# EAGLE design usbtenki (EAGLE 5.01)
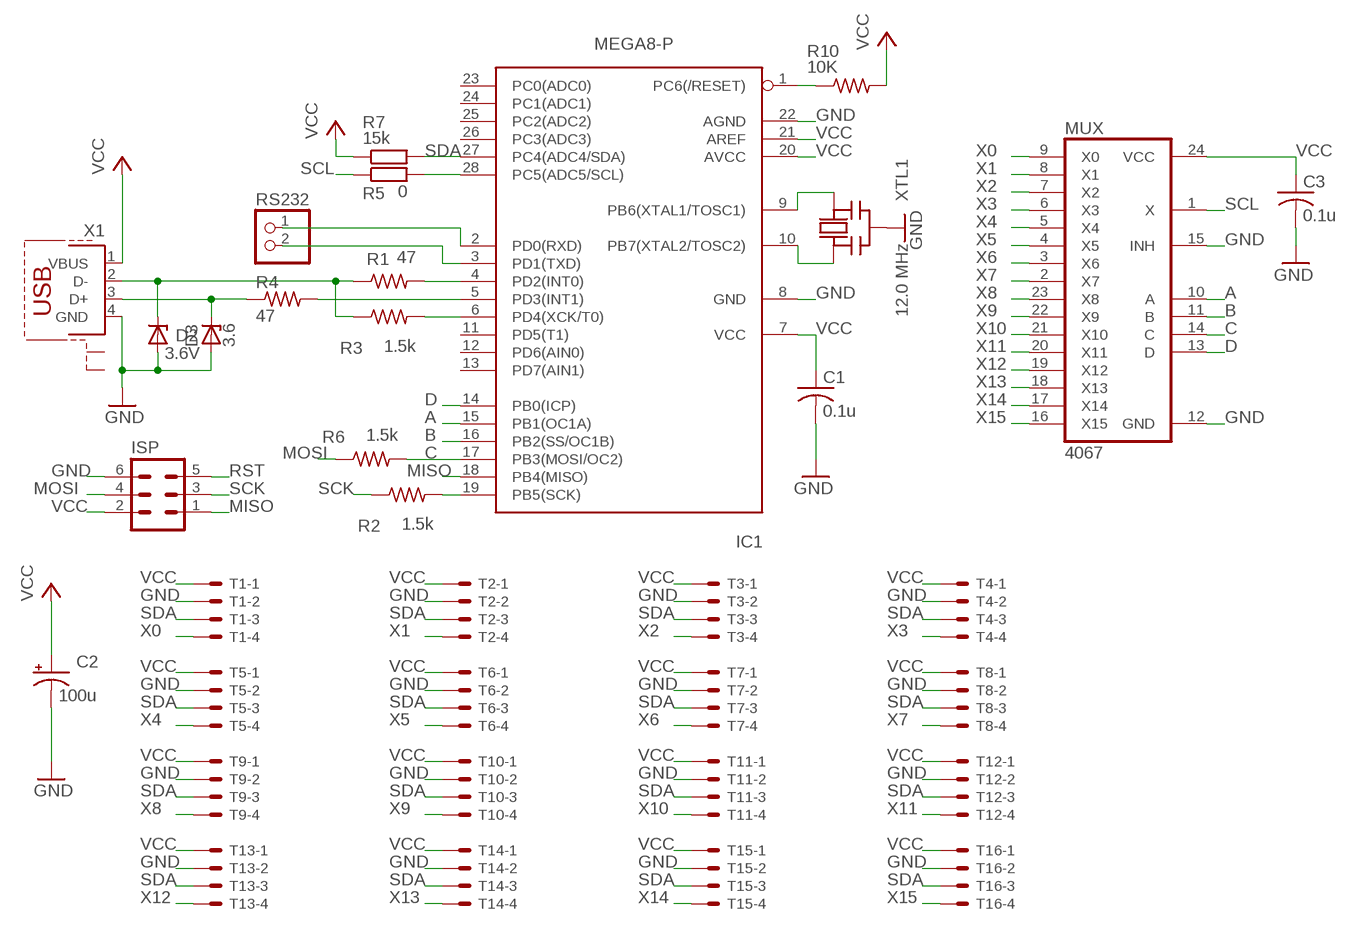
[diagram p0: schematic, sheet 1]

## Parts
C1  0.1u  C-US025-025X050  [C025-025X050]
C2  100u  CPOL-USE2.5-5  [E2,5-5]
C3  0.1u  C-US025-025X050  [C025-025X050]
D2  3.6V  ZENER-DIODEDO35Z10  [DO35Z10]
D3  3.6  ZENER-DIODEDO34-7  [DO34Z7]
IC1  MEGA8-P  [DIL28-3]
ISP  MA03-2  [MA03-2]
MUX  4067  [DIL24-6]
R1  47  R-US_0207/10  [0207/10]
R2  1.5k  R-US_0207/10  [0207/10]
R3  1.5k  R-US_0207/10  [0207/10]
R4  47  R-US_0207/5V  [0207/5V]
R5  0  R-EU_0207/12  [0207/12]
R6  1.5k  R-US_0207/10  [0207/10]
R7  15k  R-EU_0207/12  [0207/12]
R10  10K  R-US_0207/10  [0207/10]
RS232  PINHD-1X2  [1X02]
T1  C-GRID-04-70543  [70543-04]
T2  C-GRID-04-70543  [70543-04]
T3  C-GRID-04-70543  [70543-04]
T4  C-GRID-04-70543  [70543-04]
T5  C-GRID-04-70543  [70543-04]
T6  C-GRID-04-70543  [70543-04]
T7  C-GRID-04-70543  [70543-04]
T8  C-GRID-04-70543  [70543-04]
T9  C-GRID-04-70543  [70543-04]
T10  C-GRID-04-70543  [70543-04]
T11  C-GRID-04-70543  [70543-04]
T12  C-GRID-04-70543  [70543-04]
T13  C-GRID-04-70543  [70543-04]
T14  C-GRID-04-70543  [70543-04]
T15  C-GRID-04-70543  [70543-04]
T16  C-GRID-04-70543  [70543-04]
X1  USB-B_SHIELDED  [PN61729-S]
XTL1  12.0 MHz  CERMOSCILL  [CERM_OSC]

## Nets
A: IC1.15(PB1(OC1A)) MUX.10(A)
B: IC1.16(PB2(SS/OC1B)) MUX.11(B)
C: IC1.17(PB3(MOSI/OC2)) MUX.14(C) R6.2
D: IC1.14(PB0(ICP)) MUX.13(D)
D+: D3.C R4.1 X1.3(D+)
D-: D2.C R1.1 R3.1 X1.2(D-)
GND: C1.2 C2.- C3.2 D2.A D3.A IC1.8(GND) IC1.22(AGND) ISP.6 MUX.12(GND) MUX.15(INH) T1.2 T2.2 T3.2 T4.2 T5.2 T6.2 T7.2 T8.2 T9.2 T10.2 T11.2 T12.2 T13.2 T14.2 T15.2 T16.2 X1.4(GND) XTL1.P$2(GND)
MISO: IC1.18(PB4(MISO)) ISP.1
MOSI: ISP.4 R6.1
N$1: IC1.28(PC5(ADC5/SCL)) R5.2
N$2: IC1.3(PD1(TXD)) RS232.2
N$3: IC1.4(PD2(INT0)) R1.2
N$4: IC1.9(PB6(XTAL1/TOSC1)) XTL1.P$1(IN)
N$5: IC1.10(PB7(XTAL2/TOSC2)) XTL1.P$3(OUT)
N$6: IC1.5(PD3(INT1)) R4.2
N$7: IC1.6(PD4(XCK/T0)) R3.2
N$8: IC1.19(PB5(SCK)) R2.2
N$9: IC1.2(PD0(RXD)) RS232.1
RST: IC1.1(PC6(/RESET)) ISP.5 R10.1
SCK: ISP.3 R2.1
SCL: MUX.1(X) R5.1
SDA: IC1.27(PC4(ADC4/SDA)) T1.3 T2.3 T3.3 T4.3 T5.3 T6.3 T7.3 T8.3 T9.3 T10.3 T11.3 T12.3 T13.3 T14.3 T15.3 T16.3
VCC: C1.1 C2.+ C3.1 IC1.7(VCC) IC1.20(AVCC) IC1.21(AREF) ISP.2 MUX.24(VCC) R7.1 R10.2 T1.1 T2.1 T3.1 T4.1 T5.1 T6.1 T7.1 T8.1 T9.1 T10.1 T11.1 T12.1 T13.1 T14.1 T15.1 T16.1 X1.1(VBUS)
X0: MUX.9(X0) T1.4
X1: MUX.8(X1) T2.4
X2: MUX.7(X2) T3.4
X3: MUX.6(X3) T4.4
X4: MUX.5(X4) T5.4
X5: MUX.4(X5) T6.4
X6: MUX.3(X6) T7.4
X7: MUX.2(X7) T8.4
X8: MUX.23(X8) T9.4
X9: MUX.22(X9) T10.4
X10: MUX.21(X10) T11.4
X11: MUX.20(X11) T12.4
X12: MUX.19(X12) T13.4
X13: MUX.18(X13) T14.4
X14: MUX.17(X14) T15.4
X15: MUX.16(X15) T16.4
Unconnected: IC1.11(PD5(T1)) IC1.12(PD6(AIN0)) IC1.13(PD7(AIN1)) IC1.23(PC0(ADC0)) IC1.24(PC1(ADC1)) IC1.25(PC2(ADC2)) IC1.26(PC3(ADC3)) R7.2 X1.S1 X1.S2

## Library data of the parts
C1 C3 = rcl-ez:C-US: CAPACITOR, American symbol
C2 = rcl-ez:CPOL-US: POLARIZED CAPACITOR, American symbol
D2 D3 = diode:ZENER-DIODE: Z-Diode
IC1 = atmel:MEGA8-P: MICROCONTROLLER 8 Kbytes FLASH, 1 kbytes SRAM, 512 bytes EEPROM, USART, 4-channel 10 bit ADC, 2-channel 8 bit ADC Pin compatible with Atmega48, ATMega88, ATMega168 Source: avr.lbr
ISP = con-lstb:MA03-2: PIN HEADER
MUX = marios:4067: 16-channel ANALOG MULTIPLEXER
R1-R3 R6 R10 = rcl-ez:R-US_: RESISTOR, American symbol
R4 = resistor:R-US_: RESISTOR, American symbol
R5 R7 = resistor:R-EU_: RESISTOR, European symbol
RS232 = pinhead:PINHD-1X2: PIN HEADER
T1-T16 = con-molex:C-GRID-04: CONNECTOR wire to board 2.54 mm (0.100") pitch header
X1 = marios:USB-B_SHIELDED: BERG USB connector
XTL1 = minimidi:CERMOSCILL

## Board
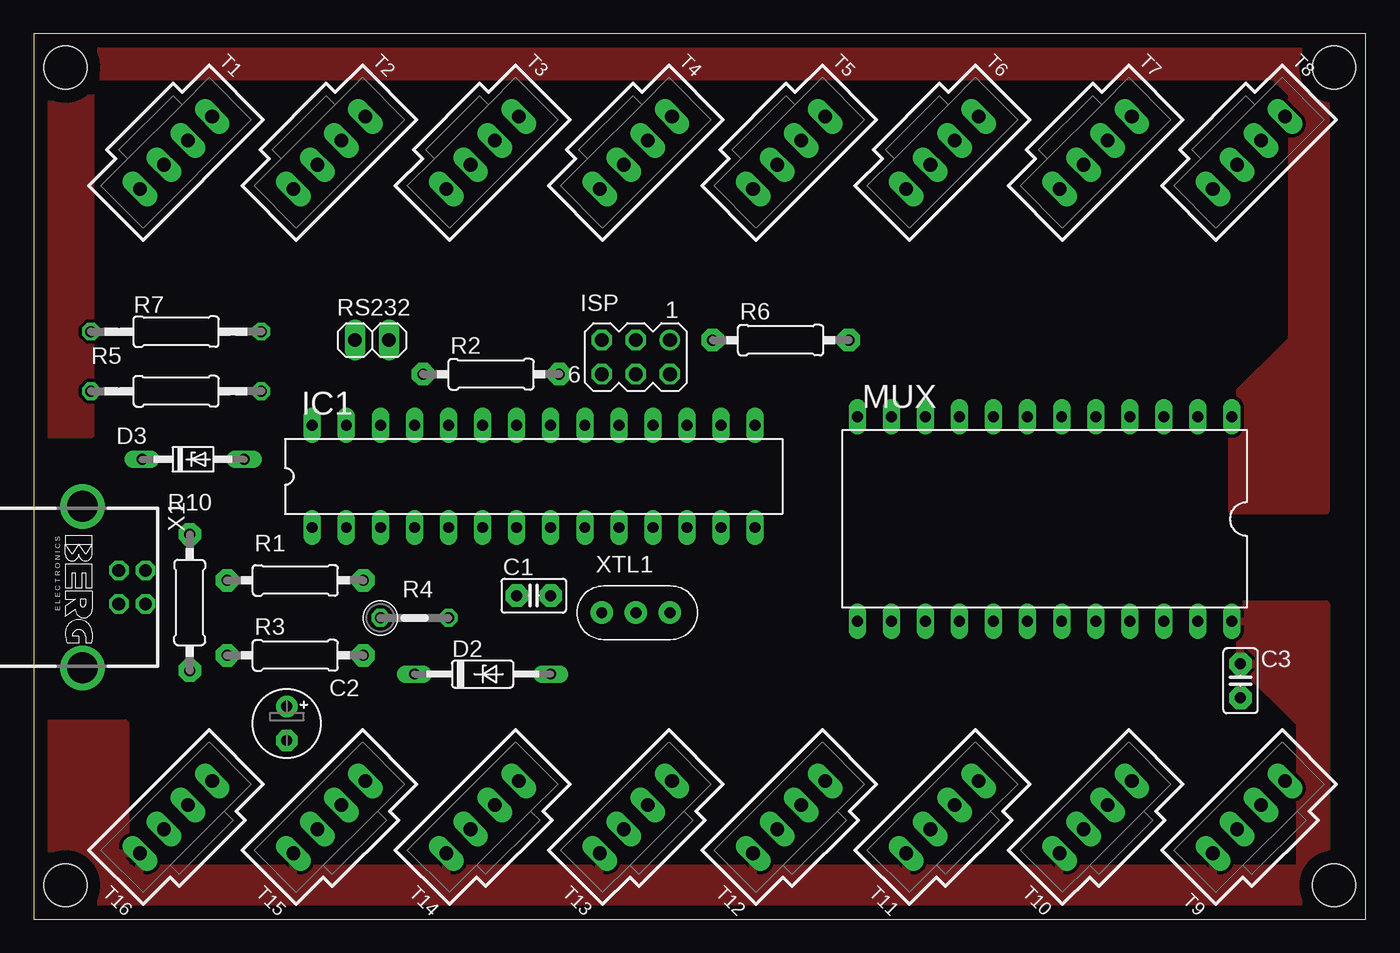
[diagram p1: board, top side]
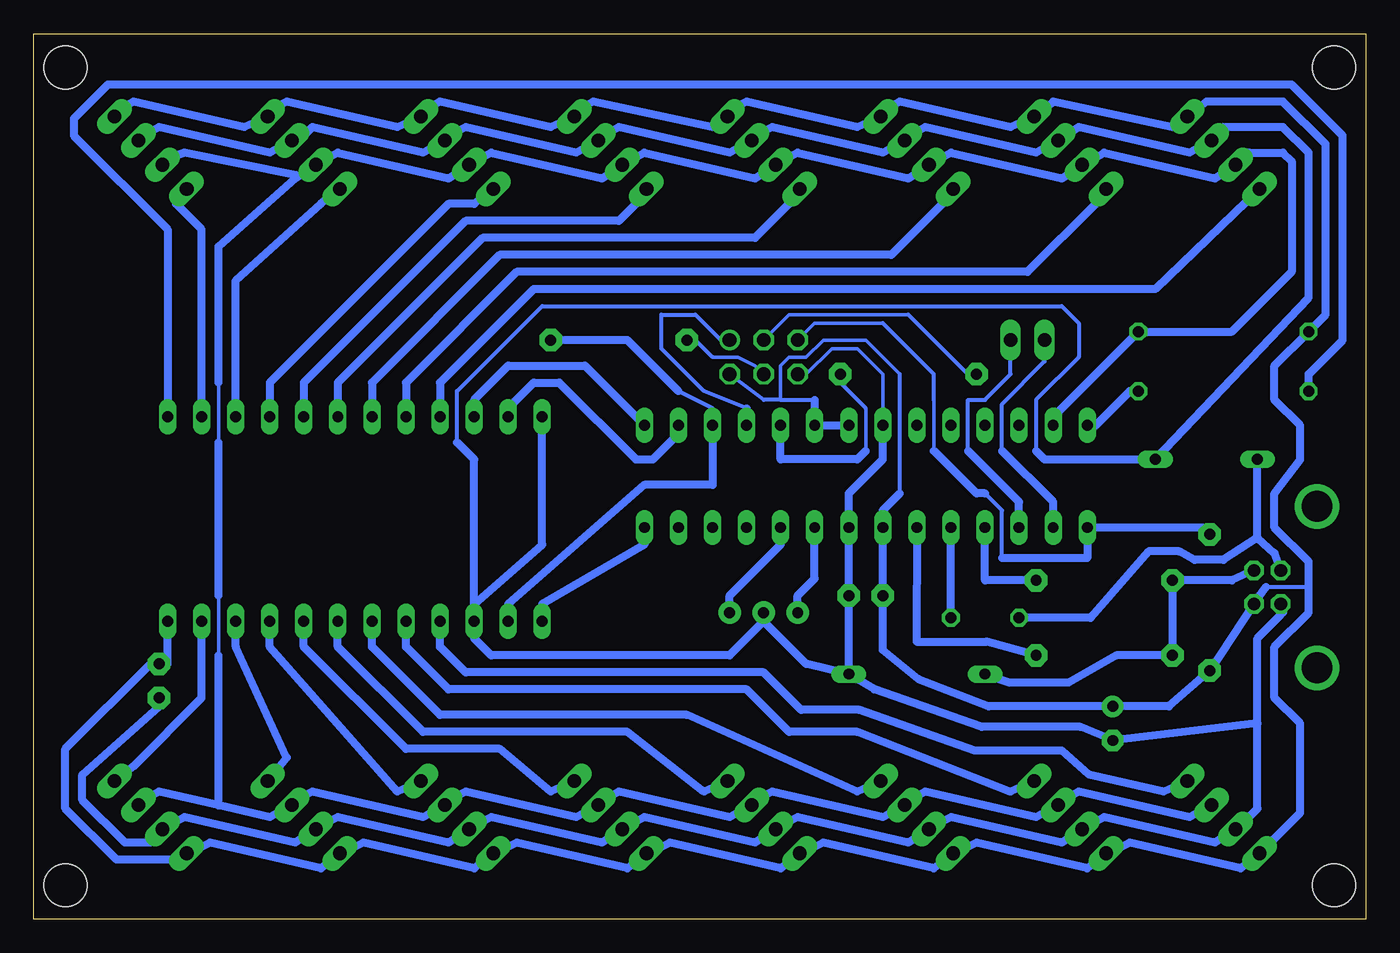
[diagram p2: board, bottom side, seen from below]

Size 99.37 x 66.03 mm. Coordinates in mm from the lower left corner, seen from the top.
Outline: 0,0 99.37,0 99.37,66.03 0,66.03 0,0
Copper layers (1*16): Top 0.035mm / dielectric 1.5mm / Bottom 0.035mm
Design rules "default *": minimum track width 10mil, minimum drill 24mil, track to track 10mil, track to pad 10mil, pad to pad 10mil, via to via 10mil, smd to smd 8mil, copper to edge 40mil, drill to drill 8mil, minimum pad ring 10mil, minimum via ring 8mil, stop-mask expansion 4mil, vias tented up to drill 0mil, thermal gap 10mil
Holes 3.2 mm at 2.38,2.54 2.38,63.49 96.99,63.49 96.99,2.54

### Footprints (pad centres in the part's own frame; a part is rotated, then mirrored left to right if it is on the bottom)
C025-025X050 = drill 0.813 pad 1.676 octagon: 1 -1.27,0; 2 1.27,0
E2,5-5 = drill 0.813 pad 1.6 round: + -1.27,0 | drill 0.813 pad 1.6 octagon: - 1.27,0
DO35Z10 = drill 0.813 long: A 5.08,0; C -5.08,0
DO34Z7 = drill 0.813 long: A 3.81,0; C -3.81,0
DIL28-3 = drill 0.813 long: 1 -16.51,-3.81; 2 -13.97,-3.81; 3 -11.43,-3.81; 4 -8.89,-3.81; 5 -6.35,-3.81; 6 -3.81,-3.81; 7 -1.27,-3.81; 8 1.27,-3.81; 9 3.81,-3.81; 10 6.35,-3.81; 11 8.89,-3.81; 12 11.43,-3.81; 13 13.97,-3.81; 14 16.51,-3.81; 15 16.51,3.81; 16 13.97,3.81; 17 11.43,3.81; 18 8.89,3.81; 19 6.35,3.81; 20 3.81,3.81; 21 1.27,3.81; 22 -1.27,3.81; 23 -3.81,3.81; 24 -6.35,3.81; 25 -8.89,3.81; 26 -11.43,3.81; 27 -13.97,3.81; 28 -16.51,3.81
MA03-2 = drill 1.016 round: 1 -2.54,-1.27 | drill 1.016 octagon: 2 -2.54,1.27; 3 0,-1.27; 4 0,1.27; 5 2.54,-1.27; 6 2.54,1.27
DIL24-6 = drill 0.813 long: 1 -13.97,-7.62; 2 -11.43,-7.62; 3 -8.89,-7.62; 4 -6.35,-7.62; 5 -3.81,-7.62; 6 -1.27,-7.62; 7 1.27,-7.62; 8 3.81,-7.62; 9 6.35,-7.62; 10 8.89,-7.62; 11 11.43,-7.62; 12 13.97,-7.62; 13 13.97,7.62; 14 11.43,7.62; 15 8.89,7.62; 16 6.35,7.62; 17 3.81,7.62; 18 1.27,7.62; 19 -1.27,7.62; 20 -3.81,7.62; 21 -6.35,7.62; 22 -8.89,7.62; 23 -11.43,7.62; 24 -13.97,7.62
0207/10 = drill 0.813 pad 1.676 octagon: 1 -5.08,0; 2 5.08,0
0207/5V = drill 0.813 octagon: 1 -2.54,0; 2 2.54,0
0207/12 = drill 0.813 octagon: 1 -6.35,0; 2 6.35,0
1X02 = drill 1.016 long: 1 -1.27,0; 2 1.27,0
70543-04 = drill 1.016 long: 1 -3.81,0; 2 -1.27,0; 3 1.27,0; 4 3.81,0
PN61729-S = drill 0.95 octagon: 1 1.25,4.71; 2 -1.25,4.71; 3 -1.25,2.71; 4 1.25,2.71 | drill 2.3 pad 2.9 round: S1 -6.02,0; S2 6.02,0
CERM_OSC = drill 0.813 pad 1.676 round: P$1 -2.54,0; P$2 0,0; P$3 2.54,0

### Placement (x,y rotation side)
C1  37.3,24.12 0 top
C2  18.89,14.6 270 top
C3  90.01,17.77 270 top
D2  33.49,18.28 0 top
D3  11.9,34.29 0 top
IC1  37.3,33.02 0 top
ISP  44.92,41.91 180 top
MUX  75.4,29.84 180 top
R1  19.52,25.27 0 top
R2  34.12,40.64 0 top
R3  19.52,19.68 0 top
R4  28.41,22.47 0 top
R5  10.63,39.37 0 top
R6  55.71,43.18 0 top
R7  10.63,43.81 0 top
R10  11.65,23.62 270 top
RS232  25.23,43.18 0 top
T1  10.63,57.15 225 top
T2  22.06,57.15 225 top
T3  33.49,57.15 225 top
T4  44.92,57.15 225 top
T5  56.35,57.15 225 top
T6  67.78,57.15 225 top
T7  79.21,57.15 225 top
T8  90.64,57.15 225 top
T9  90.64,7.62 45 top
T10  79.21,7.62 45 top
T11  67.78,7.62 45 top
T12  56.35,7.62 45 top
T13  44.92,7.62 45 top
T14  33.49,7.62 45 top
T15  22.06,7.62 45 top
T16  10.63,7.62 45 top
X1  3.65,24.76 270 top
XTL1  44.92,22.85 0 top

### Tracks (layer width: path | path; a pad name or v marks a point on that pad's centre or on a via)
A
  Bottom 0.61: MUX.10 66.51,38.73 63.97,41.27 58.25,41.27 IC1.15
B
  Bottom 0.61: MUX.11 63.97,38.09 62.06,40 60.16,40 54.45,34.29 53.17,34.29 51.27,36.19 IC1.16
C
  Bottom 0.305: IC1.17 48.73,38.09 51.27,39.37
  Bottom 0.61: 51.27,39.37 55.08,43.18 R6.2 | MUX.14 63.97,23.49 53.81,32.38 48.73,32.38 IC1.17
D
  Bottom 0.61: IC1.14 53.81,27.94 61.43,23.49 MUX.13
D+
  Bottom 0.61: 8.09,28.44 6.82,27.3 X1.3 | 8.09,28.44 10.63,26.79 12.79,26.79 13.93,27.43 16.22,27.43 20.54,22.47 R4.1 | 8.09,28.44 D3.C
D-
  Bottom 0.61: X1.2 10,25.27 R1.1 R3.1 18.63,19.68 22.19,17.65 26.5,17.65 D2.C
GND
  Bottom 0.254: ISP.6 41.74,40.64 39.84,42.54 37.93,42.54 36.03,40.64 IC1.22 | 18.76,13.33 C2.- | 90.01,15.87 C3.2
  Bottom 0.305: 67.78,35.55 67.78,39.37 61.43,45.72 22.7,45.72 21.43,44.45 21.43,41.91 24.6,38.73 24.6,34.92 | MUX.15 66.51,23.49 | 43.65,6.98 T13.2 | 55.08,6.98 T12.2 | 45.55,58.41 T4.2 | 79.84,57.78 T7.2 | 6.36,22.69 6.19,22.85
  Bottom 0.61: D2.A C1.2 IC1.8 38.57,31.75 36.03,34.29 IC1.22 | 44.92,22.22 47.46,19.68 65.24,19.68 66.51,20.95 MUX.15 | 44.92,22.22 XTL1.P$2 | 44.92,22.22 41.74,19.05 D2.A | 90.01,15.87 95.72,10.79 95.72,8.88 92.55,5.71 90.64,5.71 T9.2 89.37,6.98 88.1,7.62 79.84,5.71 T10.2 77.94,6.98 76.67,7.62 68.42,5.71 T11.2 66.51,6.98 65.24,7.62 56.98,5.71 T12.2 | D2.A 36.66,17.14 28.66,14.35 21.3,14.35 C2.- | 6.36,22.69 8.09,20.95 8.09,14.6 | 8.09,14.6 8.09,8.25 8.72,7.62 T16.2 11.27,5.71 19.52,7.62 20.79,6.98 T15.2 22.7,5.71 30.95,7.62 32.22,6.98 T14.2 34.12,5.71 42.38,7.62 43.65,6.98 | 67.78,35.55 66.51,34.29 66.51,23.49 61.43,27.94 MUX.12 | 24.6,34.92 23.96,34.29 D3.A 4.28,46.35 4.28,57.15 6.19,59.05 10.63,59.05 T1.2 13.17,57.15 21.43,59.05 T2.2 24.6,57.15 32.85,59.05 34.12,58.41 T3.2 36.03,57.15 44.28,59.05 45.55,58.41 | T13.2 45.55,5.71 53.81,7.62 55.08,6.98 | 8.09,14.6 18.76,13.33 | T4.2 47.46,57.15 55.71,59.05 56.98,58.41 T5.2 58.89,57.15 67.15,59.05 68.42,58.41 T6.2 70.32,57.15 78.58,59.05 79.84,57.78 | T7.2 81.75,57.15 90.01,59.05 91.28,58.41 T8.2 | 6.19,22.85 X1.4
MISO
  Bottom 0.305: 46.19,38.09 49.36,39.37 52.54,42.54 52.54,45.08 50,45.08 48.09,43.18 ISP.1
  Bottom 0.61: IC1.18 46.19,38.09
MOSI
  Bottom 0.254: 48.73,41.91 46.82,41.91 45.55,41.27 ISP.4
  Bottom 0.305: 48.73,41.91 50,43.18 R6.1
N$1
  Bottom 0.61: R5.2 17.62,39.37 20.16,36.83 IC1.28
N$2
  Bottom 0.305: 29.68,34.92 29.68,38.73 28.41,38.73 26.5,40.64 RS232.2
  Bottom 0.61: IC1.3 25.87,31.11 29.68,34.92
N$3
  Bottom 0.61: IC1.4 28.41,25.27 R1.2
N$4
  Bottom 0.61: IC1.9 41.11,25.4 42.38,24.12 XTL1.P$1
N$5
  Bottom 0.61: IC1.10 43.65,27.94 47.46,24.12 XTL1.P$3
N$6
  Bottom 0.61: R4.2 IC1.5
N$7
  Bottom 0.61: R3.2 28.28,20.7 33.51,20.7 IC1.6
N$8
  Bottom 0.254: 37.3,34.92 37.3,38.09
  Bottom 0.305: 37.3,38.09 39.2,40 R2.2
  Bottom 0.61: 37.3,34.92 37.93,34.29 43.65,34.29 IC1.19
N$9
  Bottom 0.305: 27.14,34.92 27.14,38.41 23.96,41.59 RS232.1
  Bottom 0.61: IC1.2 23.33,31.11 27.14,34.92
RST
  Bottom 0.254: 32.22,34.92 32.22,38.73 | 36.03,44.45 41.11,44.45 ISP.5
  Bottom 0.305: 36.03,44.45 32.22,40.64 32.22,38.73 | 27.14,26.92 27.14,30.48 28.41,31.75
  Bottom 0.61: R10.1 12.18,29.21 IC1.1 20.79,26.92 27.14,26.92 | 32.22,34.92 29.05,31.75 28.41,31.75
SCK
  Bottom 0.254: 34.12,45.08 43.01,45.08 ISP.3
  Bottom 0.305: 34.12,45.08 29.68,40.64 R2.1
SCL
  Bottom 0.61: R5.1 4.28,40.64 1.74,43.18 1.74,58.41 5.55,62.23 93.81,62.23 96.36,59.68 96.36,58.41 89.37,51.43 MUX.1
SCL1
  pour Top: 1.1,36.19 4.28,36.19 4.28,62.86 92.55,62.86 93.81,61.59 93.81,43.18 89.37,38.73 89.37,30.48 96.36,30.48 96.36,66.03 1.1,65.4
SDA
  Bottom 0.254: 85.56,19.68 85.56,24.12 | 85.56,35.55 85.56,40
  Bottom 0.305: 22.7,8.88 T15.3 | 34.12,8.88 T14.3 | 45.55,8.88 T13.3 | 56.98,8.88 T12.3 | 85.56,8.49 85.56,8.5 85.56,8.88 | T3.3 32.22,56.51 | T4.3 43.65,56.51 | T7.3 77.94,56.51 | 90.01,56.51 T8.3
  Bottom 0.61: 85.56,8.88 85.56,19.68 | 85.56,24.12 85.56,35.55 | 85.56,40 85.56,50.16 79.84,55.24 | T16.3 13.17,7.62 21.43,9.52 22.7,8.88 | T15.3 24.6,7.62 32.85,9.52 34.12,8.88 | T14.3 36.03,7.62 44.28,9.52 45.55,8.88 | T13.3 47.46,7.62 55.71,9.52 56.98,8.88 | T12.3 58.89,7.62 67.15,9.52 68.42,8.88 T11.3 70.32,7.62 78.58,9.52 79.84,8.88 T10.3 81.75,7.62 85.56,8.49 90.01,9.52 91.28,8.88 T9.3 | 32.22,56.51 30.95,57.15 22.7,55.24 T2.3 19.52,57.15 11.27,55.24 T1.3 8.72,57.15 6.19,57.15 5.55,56.51 5.55,48.26 10,43.81 16.98,43.81 23.33,37.46 IC1.27 | T3.3 34.12,55.24 42.38,57.15 43.65,56.51 | T4.3 45.55,55.24 53.81,57.15 55.08,56.51 T5.3 56.98,55.24 65.24,57.15 66.51,56.51 T6.3 68.42,55.24 76.67,57.15 77.94,56.51 | 79.84,55.24 T7.3 | 79.84,55.24 79.79,55.47 88.1,57.15 90.01,56.51
VCC
  Bottom 0.254: 43.65,38.73 43.65,41.27 43.01,41.91 41.74,41.91 40.47,43.18 37.3,43.18 34.76,40.64
  Bottom 0.305: 41.11,38.73 43.65,38.73 44.92,38.73 ISP.2 | 4.28,24.76 7.46,24.76 | 18.89,5.08 T15.1 | 41.74,5.08 T13.1 | 53.17,5.08 T12.1 | 93.18,60.32 T8.1 | 34.76,31.75 34.76,40.64 | IC1.7 36.03,30.48
  Bottom 0.61: IC1.21 IC1.20 41.11,38.73 | IC1.7 C1.1 36.03,20.06 33.36,17.9 28.16,15.87 C2.+ 14.69,15.87 R10.2 X1.1 7.46,24.76 | MUX.24 89.37,19.05 C3.1 90.64,19.05 96.99,12.69 96.99,8.25 93.18,4.44 88.73,4.44 T9.1 87.47,5.08 86.2,5.71 77.94,3.8 T10.1 76.04,5.08 74.77,5.71 66.51,3.8 T11.1 64.61,5.08 63.33,5.71 55.08,3.8 T12.1 | 18.89,5.08 17.62,5.71 9.36,3.8 T16.1 4.92,7.94 4.92,14.6 6.82,16.51 6.82,20.31 4.28,22.85 4.28,24.76 4.28,26.66 6.82,29.21 6.82,31.75 4.92,34.29 4.92,36.83 6.82,38.73 6.82,41.27 R7.1 3.01,45.08 3.01,57.78 6.19,60.96 11.9,60.96 T1.1 14.44,59.05 23.33,60.96 T2.1 26.5,59.05 34.76,60.96 36.03,60.32 T3.1 37.93,59.05 46.19,60.96 47.46,60.32 T4.1 48.73,59.05 57.62,60.96 58.89,60.32 T5.1 60.79,59.05 69.05,60.96 70.32,60.32 T6.1 72.23,59.05 80.48,60.96 81.75,60.32 T7.1 83.66,59.05 91.91,60.96 93.18,60.32 | T15.1 20.79,3.8 29.05,5.71 30.32,5.08 T14.1 32.22,3.8 40.47,5.71 41.74,5.08 | T13.1 43.65,3.8 51.9,5.71 53.17,5.08 | 36.03,30.48 34.76,31.75
  pour Top: 1.1,14.6 6.82,14.6 6.82,3.8 94.45,3.8 94.45,14.6 90.01,19.05 90.01,23.49 96.36,23.49 96.36,-1.91 1.1,-1.27
X0
  Bottom 0.61: MUX.9 69.05,40 62.06,46.98 15.71,46.98 T1.4
X1
  Bottom 0.61: MUX.8 71.59,40 63.33,48.26 25.23,48.26 20.16,53.34 T2.4
X2
  Bottom 0.61: MUX.7 74.13,40 64.61,49.52 35.39,49.52 31.59,53.34 T3.4
X3
  Bottom 0.61: MUX.6 76.67,40 65.88,50.8 45.55,50.8 43.01,53.34 T4.4
X4
  Bottom 0.61: MUX.5 79.21,40 67.15,52.07 55.71,52.07 54.45,53.34 T5.4
X5
  Bottom 0.61: MUX.4 81.75,40 68.42,53.34 66.51,53.34 T6.4
X6
  Bottom 0.61: MUX.3 84.29,47.62 77.94,53.34 T7.4
X7
  Bottom 0.61: MUX.2 86.83,51.43 88.73,53.34 T8.4
X8
  Bottom 0.61: MUX.23 86.83,16.51 91.91,11.42 T9.4
X9
  Bottom 0.61: MUX.22 84.29,20.31 80.48,12.06 T10.4
X10
  Bottom 0.61: MUX.21 81.75,20.31 72.23,9.52 T11.4
X11
  Bottom 0.61: MUX.20 79.21,20.31 71.59,12.69 64.61,12.69 60.79,9.52 T12.4
X12
  Bottom 0.61: MUX.19 76.67,20.31 70.32,13.97 55.08,13.97 49.36,9.52 T13.4
X13
  Bottom 0.61: MUX.18 74.13,20.31 69.05,15.24 50.63,15.24 37.93,9.52 T14.4
X14
  Bottom 0.61: MUX.17 71.59,20.31 68.42,17.14 46.19,17.14 43.01,13.97 37.93,13.97 26.5,9.52 T15.4
X15
  Bottom 0.61: MUX.16 69.05,20.31 67.15,18.41 44.92,18.41 42.13,15.62 37.81,15.62 29.17,12.57 22.7,12.57 20.66,10.79 15.08,9.52 T16.4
